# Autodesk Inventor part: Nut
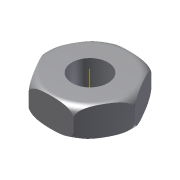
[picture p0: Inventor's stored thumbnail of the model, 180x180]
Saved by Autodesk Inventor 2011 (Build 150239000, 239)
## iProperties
Created: 2009-04
Part Number: Nut
Document SubType Name: Modeling
Designer: Sham
Density: 1 g/cm^3
Author: Sham
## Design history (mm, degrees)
sketch "Sketch1"
  geometry: L1 (7.5, 12.99)-(15, 0); L2 (15, 0)-(7.5, -12.99); L3 (7.5, -12.99)-(-7.5, -12.99); L4 (-7.5, -12.99)-(-15, 0); L5 (-15, 0)-(-7.5, 12.99); L6 (-7.5, 12.99)-(7.5, 12.99); C1 r 6 at (0, 0); 1 further point
  constraints: 12 end point, 1 centre point, 1 coincident, 13 other
  dimensions: "d0" = 30 distance of L1.end L4.end; "d1" = 12 diameter of C1
extrude "Extrusion1" new body sketch "Sketch1" distance "d2" = 12; taper "d3" = 0 deg
sketch "Sketch2"
  geometry: L1 (-12, 0)-(-12, -0.022); L2 (-15, 7)-(-15, 3); L3 (0, -2.87)-(0, 12.87) reference; A1 r 3 centre (-12, 7) between (-12, 10) and (-15, 7); A2 r 3 centre (-12, 3) between (-15, 3) and (-12, 0)
  constraints: 4 end point, 4 point on circle, 2 centre point, 1 tangent
revolve "Revolution1" sketch "Sketch2" stored, may be unused: angle "d7" = 90 deg
body "Solid1"
other parameters: "d6" = 90 deg
